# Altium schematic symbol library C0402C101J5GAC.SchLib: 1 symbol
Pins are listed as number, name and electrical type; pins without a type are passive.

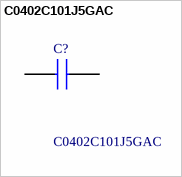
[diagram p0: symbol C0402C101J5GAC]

## C0402C101J5GAC
designator C?
Multilayer Ceramic Capacitors MLCC - SMD/SMT 50volts 100pF 5% C0G; Manufacturer_Name: Yageo Group; Geometry.Height: 0.55mm
footprint C0402C104J4RACTU
pins: 1, 2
